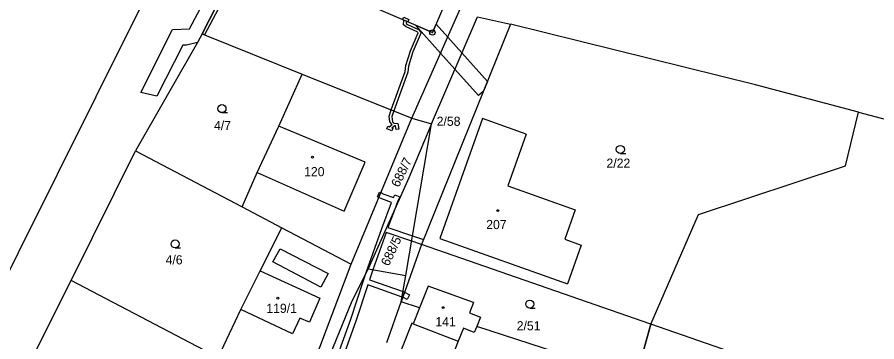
# Model space of a CAD drawing. Extents: x -747333 to -745433, y -1133152 to -1130600.
# Drawn here: x -746143.6 to -745983.7, y -1131522.4 to -1131462 of the extents above; entities that cross this region are included whole.
import ezdxf

# ---------------------------------------------------------------- set-up
doc = ezdxf.new("R2010")
doc.units = 0
for name, color, linetype in [('Vrstva 1', 7, 'Continuous'), ('Vrstva 18', 7, 'Continuous'), ('Vrstva 19', 7, 'Continuous'), ('Vrstva 24', 7, 'Continuous'), ('Vrstva 25', 7, 'Continuous'), ('Vrstva 3', 7, 'Continuous'), ('Vrstva 30', 7, 'Continuous'), ('Vrstva 37', 7, 'Continuous'), ('Vrstva 4', 7, 'Continuous'), ('Vrstva 52', 7, 'Continuous'), ('Vrstva 6', 7, 'Continuous')]:
    doc.layers.add(name, color=color, linetype=linetype)

msp = doc.modelspace()

# ---------------------------------------------------------------- linework, layer by layer
at = {"layer": 'Vrstva 1'}
for p, q in [((-746055.78, -1131440.25), (-746066.38, -1131464.83)), ((-746066.38, -1131464.83), (-746095.3, -1131452.34))]:
    msp.add_line(p, q, dxfattribs=at)
for points in [[(-746090.75, -1131400.54), (-746121.73, -1131462.2)], [(-746099.65, -1131446.33), (-746109.2, -1131465.08)], [(-746070.2, -1131480.79), (-746055.46, -1131447.33)], [(-746121.73, -1131462.2), (-746150.71, -1131520.43)], [(-746066.53, -1131481.86), (-746058.01, -1131461.89)], [(-746058.01, -1131461.89), (-746051.84, -1131463.28)], [(-746051.84, -1131463.28), (-746068.39, -1131504.28)], [(-746006.29, -1131474.57), (-746051.84, -1131463.28)], [(-746109.2, -1131465.08), (-746110.05, -1131466.67)], [(-746109.2, -1131465.08), (-746108.75, -1131465.26)], [(-746108.75, -1131465.26), (-746090.62, -1131472.56)], [(-746110.05, -1131466.67), (-746121.6, -1131486.86)], [(-746094.92, -1131482.29), (-746090.62, -1131472.56)], [(-746090.62, -1131472.56), (-746070.2, -1131480.79)], [(-745987.12, -1131479.66), (-746006.29, -1131474.57)], [(-745989.55, -1131489.64), (-745987.12, -1131479.66)], [(-745987.12, -1131479.66), (-745954.58, -1131488.31)], [(-746081.52, -1131507.94), (-746070.2, -1131480.79)], [(-746071.31, -1131510.04), (-746066.53, -1131481.86)], [(-746070.2, -1131480.79), (-746066.53, -1131481.86)], [(-746057.08, -1131480.84), (-746065.02, -1131503.16)], [(-746048.95, -1131483.73), (-746057.08, -1131480.84)], [(-746098.99, -1131490.89), (-746094.92, -1131482.29)], [(-746048.95, -1131483.73), (-746052.32, -1131493.39)], [(-746133.59, -1131510.98), (-746121.6, -1131486.86)], [(-746121.6, -1131486.86), (-746101.76, -1131497.26)], [(-746016.9, -1131498.7), (-745989.55, -1131489.64)], [(-746101.76, -1131497.26), (-746098.99, -1131490.89)], [(-746052.32, -1131493.39), (-746039.8, -1131497.85)], [(-746101.76, -1131497.26), (-746094.4, -1131501.22)], [(-746039.8, -1131497.85), (-746041.76, -1131503.33)], [(-746025.75, -1131519.12), (-746016.9, -1131498.7)], [(-746098.43, -1131509.2), (-746094.4, -1131501.22)], [(-746094.4, -1131501.22), (-746081.52, -1131507.94)], [(-746068.39, -1131504.28), (-746072.17, -1131514.96)], [(-746025.75, -1131519.12), (-746068.39, -1131504.28)], [(-746065.02, -1131503.16), (-746041.26, -1131511.62)], [(-746041.76, -1131503.33), (-746038.7, -1131504.42)], [(-746038.7, -1131504.42), (-746041.26, -1131511.62)], [(-746089.64, -1131529.49), (-746081.52, -1131507.94)], [(-746102, -1131516.42), (-746098.43, -1131509.2)], [(-746072.17, -1131514.96), (-746071.31, -1131510.04)], [(-746142.23, -1131528.33), (-746133.59, -1131510.98)], [(-746106.2, -1131525.3), (-746133.59, -1131510.98)], [(-746067.15, -1131512.07), (-746068.75, -1131516.07)], [(-746058.72, -1131515.11), (-746067.15, -1131512.07)], [(-746074.85, -1131522.52), (-746072.17, -1131514.96)], [(-746068.75, -1131516.07), (-746072.17, -1131514.96)], [(-746058.72, -1131515.11), (-746059.47, -1131517)], [(-746106.2, -1131525.3), (-746102, -1131516.42)], [(-746059.47, -1131517), (-746057.45, -1131517.8)], [(-746057.45, -1131517.8), (-746058.14, -1131519.53)], [(-746060.61, -1131519.88), (-746061.57, -1131522.3)], [(-746058.59, -1131520.68), (-746060.61, -1131519.88)], [(-746058.14, -1131519.53), (-746058.59, -1131520.68)], [(-746028.56, -1131529.17), (-746058.14, -1131519.53)], [(-746025.75, -1131519.12), (-746028.56, -1131529.17)], [(-746005.02, -1131526.33), (-746025.75, -1131519.12)], [(-746061.57, -1131522.3), (-746063.44, -1131527.04)]]:
    msp.add_lwpolyline(points, dxfattribs=at)
at = {"layer": 'Vrstva 24'}
msp.add_line((-746066.43, -1131464.83), (-746066.33, -1131464.83), dxfattribs=at)
msp.add_circle((-746066.38, -1131464.83), 0.499289, dxfattribs=at)
at = {"layer": 'Vrstva 25'}
for p, q in [((-746105.52, -1131479.75), (-746104.52, -1131479.75)), ((-746031.43, -1131487.35), (-746030.43, -1131487.35)), ((-746114.23, -1131504.94), (-746113.23, -1131504.94)), ((-746048.27, -1131516.13), (-746047.27, -1131516.13))]:
    msp.add_line(p, q, dxfattribs=at)
for centre, radius in [((-746105.52, -1131479), 0.75), ((-746031.43, -1131486.6), 0.75), ((-746088.7, -1131488.05), 0.174503), ((-746054.23, -1131497.99), 0.174503), ((-746114.23, -1131504.19), 0.75), ((-746095.13, -1131514.27), 0.174503), ((-746048.27, -1131515.38), 0.75), ((-746064.36, -1131516.05), 0.174503)]:
    msp.add_circle(centre, radius, dxfattribs=at)
at = {"layer": 'Vrstva 3'}
for points in [[(-746057.08, -1131480.84), (-746065.02, -1131503.16)], [(-746048.95, -1131483.73), (-746057.08, -1131480.84)], [(-746098.99, -1131490.89), (-746094.92, -1131482.29)], [(-746078.88, -1131488.97), (-746094.92, -1131482.29)], [(-746048.95, -1131483.73), (-746052.32, -1131493.39)], [(-746082.79, -1131498.11), (-746078.88, -1131488.97)], [(-746098.99, -1131490.89), (-746082.79, -1131498.11)], [(-746052.32, -1131493.39), (-746039.8, -1131497.85)], [(-746039.8, -1131497.85), (-746041.76, -1131503.33)], [(-746065.02, -1131503.16), (-746041.26, -1131511.62)], [(-746041.76, -1131503.33), (-746038.7, -1131504.42)], [(-746038.7, -1131504.42), (-746041.26, -1131511.62)], [(-746102, -1131516.42), (-746098.43, -1131509.2)], [(-746098.43, -1131509.2), (-746087.32, -1131514.31)], [(-746067.15, -1131512.07), (-746068.75, -1131516.07)], [(-746058.72, -1131515.11), (-746067.15, -1131512.07)], [(-746087.32, -1131514.31), (-746089.24, -1131518.76)], [(-746058.72, -1131515.11), (-746059.47, -1131517)], [(-746092.41, -1131520.95), (-746102, -1131516.42)], [(-746068.75, -1131516.07), (-746069.95, -1131519.06)], [(-746059.47, -1131517), (-746057.45, -1131517.8)], [(-746091.06, -1131518), (-746092.41, -1131520.95)], [(-746089.24, -1131518.76), (-746091.06, -1131518)], [(-746057.45, -1131517.8), (-746058.14, -1131519.53)], [(-746069.95, -1131519.06), (-746061.57, -1131522.3)], [(-746060.61, -1131519.88), (-746061.57, -1131522.3)], [(-746058.59, -1131520.68), (-746060.61, -1131519.88)], [(-746058.14, -1131519.53), (-746058.59, -1131520.68)]]:
    msp.add_lwpolyline(points, dxfattribs=at)
at = {"layer": 'Vrstva 30'}
for p, q in [((-746071.92, -1131462.44), (-746071.72, -1131461.98)), ((-746071.69, -1131462.54), (-746071.92, -1131462.44)), ((-746071.76, -1131463.38), (-746071.69, -1131462.54)), ((-746071.72, -1131461.98), (-746070.77, -1131462.39)), ((-746071.2, -1131462.75), (-746071.24, -1131463.16)), ((-746070.97, -1131462.85), (-746071.2, -1131462.75)), ((-746070.77, -1131462.39), (-746070.97, -1131462.85)), ((-746071.25, -1131463.79), (-746071.76, -1131463.38)), ((-746069.24, -1131464.7), (-746071.25, -1131463.79)), ((-746071.24, -1131463.16), (-746070.99, -1131463.35)), ((-746070.99, -1131463.35), (-746068.94, -1131464.28)), ((-746064.87, -1131468.68), (-746069.53, -1131463.47)), ((-746069.53, -1131463.47), (-746066.38, -1131464.83)), ((-746068.94, -1131464.28), (-746068.47, -1131464.8)), ((-746066.38, -1131464.83), (-746065.7, -1131463.25)), ((-746065.7, -1131463.25), (-746063.54, -1131465.67)), ((-746070.48, -1131468.26), (-746069.05, -1131464.9)), ((-746068.47, -1131464.8), (-746070, -1131468.44)), ((-746069.05, -1131464.9), (-746069.24, -1131464.7)), ((-746063.54, -1131465.67), (-746060.89, -1131468.63)), ((-746071.31, -1131470.99), (-746070.48, -1131468.26)), ((-746070, -1131468.44), (-746070.81, -1131471.09)), ((-746062.19, -1131471.68), (-746064.87, -1131468.68)), ((-746060.89, -1131468.63), (-746056.14, -1131473.93)), ((-746074.02, -1131479.25), (-746071.44, -1131472.12)), ((-746070.96, -1131472.24), (-746073.56, -1131479.44)), ((-746071.44, -1131472.12), (-746071.31, -1131470.99)), ((-746070.81, -1131471.09), (-746070.96, -1131472.24)), ((-746057.81, -1131476.57), (-746062.19, -1131471.68)), ((-746056.14, -1131473.93), (-746056.86, -1131475.72)), ((-746056.86, -1131475.72), (-746057.81, -1131476.57)), ((-746074.44, -1131480.39), (-746074.02, -1131479.25)), ((-746073.56, -1131479.44), (-746073.92, -1131480.45)), ((-746074.31, -1131481.44), (-746074.44, -1131480.39)), ((-746073.88, -1131481.96), (-746074.31, -1131481.44)), ((-746073.92, -1131480.45), (-746073.81, -1131481.44)), ((-746073.81, -1131481.44), (-746073.54, -1131481.72)), ((-746073.54, -1131481.72), (-746072.78, -1131481.75)), ((-746072.78, -1131481.75), (-746072.64, -1131482.82)), ((-746074.86, -1131482.75), (-746074.66, -1131482.29)), ((-746073.94, -1131483.16), (-746074.86, -1131482.75)), ((-746074.66, -1131482.29), (-746074.44, -1131482.39)), ((-746074.44, -1131482.39), (-746073.88, -1131481.96)), ((-746073.74, -1131482.7), (-746073.94, -1131483.16)), ((-746073.38, -1131482.22), (-746073.93, -1131482.62)), ((-746073.93, -1131482.62), (-746073.74, -1131482.7)), ((-746073.22, -1131482.23), (-746073.38, -1131482.22)), ((-746073.14, -1131482.88), (-746073.22, -1131482.23)), ((-746072.64, -1131482.82), (-746073.14, -1131482.88))]:
    msp.add_line(p, q, dxfattribs=at)
for points in [[(-746114.69, -1131464.25), (-746111.55, -1131464.15), (-746102.76, -1131447.52), (-746102.23, -1131441.33)], [(-746099.65, -1131446.33), (-746109.2, -1131465.08), (-746110.05, -1131466.67), (-746112.12, -1131467.17)], [(-746103.18, -1131454.73), (-746108.75, -1131465.26), (-746109.2, -1131465.08), (-746099.65, -1131446.33)], [(-746071.2, -1131462.75), (-746071.69, -1131462.54)], [(-746071.69, -1131462.54), (-746071.2, -1131462.75)], [(-746112.12, -1131467.17), (-746112.81, -1131467.19), (-746117.62, -1131476.71), (-746120.61, -1131475.98), (-746114.69, -1131464.25)], [(-746076.62, -1131495.43), (-746076.2, -1131494.53)], [(-746076.2, -1131494.53), (-746075.97, -1131494.63)], [(-746075.97, -1131494.63), (-746075.39, -1131494.9)], [(-746076.36, -1131495.55), (-746076.62, -1131495.43)], [(-746075.77, -1131495.82), (-746076.36, -1131495.55)], [(-746073.97, -1131496.45), (-746075.77, -1131495.82)], [(-746075.39, -1131494.9), (-746073.59, -1131495.53)], [(-746073.59, -1131495.53), (-746073.36, -1131495.02)], [(-746072.86, -1131496.34), (-746073.45, -1131497.92)], [(-746073.36, -1131495.02), (-746072.45, -1131495.44)], [(-746072.45, -1131495.44), (-746072.86, -1131496.34)], [(-746075.78, -1131501.29), (-746073.97, -1131496.45)], [(-746073.45, -1131497.92), (-746074.66, -1131501.15)], [(-746078.68, -1131509.53), (-746075.78, -1131501.29)], [(-746075.01, -1131502.09), (-746077.43, -1131508.99)], [(-746070.23, -1131503.67), (-746075.01, -1131502.09)], [(-746074.66, -1131501.15), (-746070.06, -1131502.69)], [(-746070.06, -1131502.69), (-746068.03, -1131503.38)], [(-746068.39, -1131504.28), (-746070.23, -1131503.67)], [(-746068.03, -1131503.38), (-746068.39, -1131504.28)], [(-746077.43, -1131508.99), (-746078.08, -1131510.85)], [(-746079.19, -1131510.99), (-746078.68, -1131509.53)], [(-746081.56, -1131518.21), (-746079.19, -1131510.99)], [(-746078.41, -1131511.79), (-746080.62, -1131518.54)], [(-746072.01, -1131514.07), (-746078.41, -1131511.79)], [(-746078.08, -1131510.85), (-746071.84, -1131513.07)], [(-746071.54, -1131513.18), (-746071.87, -1131514.12)], [(-746071.87, -1131514.12), (-746071.54, -1131513.18)], [(-746071.84, -1131513.07), (-746071.54, -1131513.18)], [(-746071.54, -1131513.18), (-746070.62, -1131513.66)], [(-746070.62, -1131513.66), (-746071.09, -1131514.55)], [(-746071.87, -1131514.12), (-746072.01, -1131514.07)], [(-746071.09, -1131514.55), (-746071.87, -1131514.12)], [(-746084.15, -1131525.41), (-746081.56, -1131518.21)], [(-746080.62, -1131518.54), (-746083.37, -1131526.22)]]:
    msp.add_lwpolyline(points, dxfattribs=at)
at = {"layer": 'Vrstva 37'}
for centre in [(-746088.7, -1131488.05), (-746054.23, -1131497.99), (-746095.13, -1131514.27), (-746064.36, -1131516.05)]:
    msp.add_circle(centre, 0.174503, dxfattribs=at)
at = {"layer": 'Vrstva 4'}
for points in [[(-746078.88, -1131488.97), (-746094.92, -1131482.29)], [(-746082.79, -1131498.11), (-746078.88, -1131488.97)], [(-746098.99, -1131490.89), (-746082.79, -1131498.11)], [(-746094.67, -1131505.08), (-746085.75, -1131509.67), (-746087.16, -1131512.22), (-746096.03, -1131507.54), (-746094.67, -1131505.08)], [(-746098.43, -1131509.2), (-746087.32, -1131514.31)], [(-746087.32, -1131514.31), (-746089.24, -1131518.76)], [(-746092.41, -1131520.95), (-746102, -1131516.42)], [(-746068.75, -1131516.07), (-746069.95, -1131519.06)], [(-746091.06, -1131518), (-746092.41, -1131520.95)], [(-746089.24, -1131518.76), (-746091.06, -1131518)], [(-746070.19, -1131518.96), (-746072.11, -1131523.76)], [(-746069.95, -1131519.06), (-746070.19, -1131518.96)], [(-746069.95, -1131519.06), (-746061.57, -1131522.3)]]:
    msp.add_lwpolyline(points, dxfattribs=at)
at = {"layer": 'Vrstva 52'}
msp.add_lwpolyline([(-746010.44, -1131534), (-746026.3, -1131529.91), (-746028.56, -1131529.17), (-746025.75, -1131519.12), (-746016.9, -1131498.7), (-745989.55, -1131489.64), (-745987.12, -1131479.66), (-745954.58, -1131488.31), (-745953.84, -1131486.8), (-745949.25, -1131488), (-745940.31, -1131468.87), (-745927.94, -1131443.38)], dxfattribs=at)
at = {"layer": 'Vrstva 6'}
for points in [[(-746066.53, -1131481.86), (-746070.75, -1131491.89)], [(-746070.75, -1131491.89), (-746078.33, -1131508.83)], [(-746078.33, -1131508.83), (-746081.34, -1131514.84)], [(-746078.33, -1131508.83), (-746071.31, -1131510.04)], [(-746081.34, -1131514.84), (-746086.66, -1131527.76)]]:
    msp.add_lwpolyline(points, dxfattribs=at)

# ---------------------------------------------------------------- texts
at = {"layer": 'Vrstva 18'}
for s, p in [('4/7', (-746107, -1131483)), ('2/58', (-746065.58, -1131482.2)), ('2/22', (-746034, -1131490)), ('4/6', (-746116, -1131508)), ('2/51', (-746050.7, -1131520.27))]:
    msp.add_text(s, height=1.7, dxfattribs=at).set_placement(p)
for s, rotation, p in [('688/7', 63.85086, (-746072.6309, -1131493.774132)), ('688/5', 64.62162, (-746074.51, -1131508.44))]:
    msp.add_text(s, height=1.7, rotation=rotation, dxfattribs=at).set_placement(p)
at = {"layer": 'Vrstva 19'}
for s, p in [('120', (-746090.24, -1131491.58)), ('207', (-746056.37, -1131501.42)), ('119/1', (-746097.270483, -1131517.02)), ('141', (-746065.82, -1131519.51))]:
    msp.add_text(s, height=1.7, dxfattribs=at).set_placement(p)

doc.saveas('drawing.dxf')
